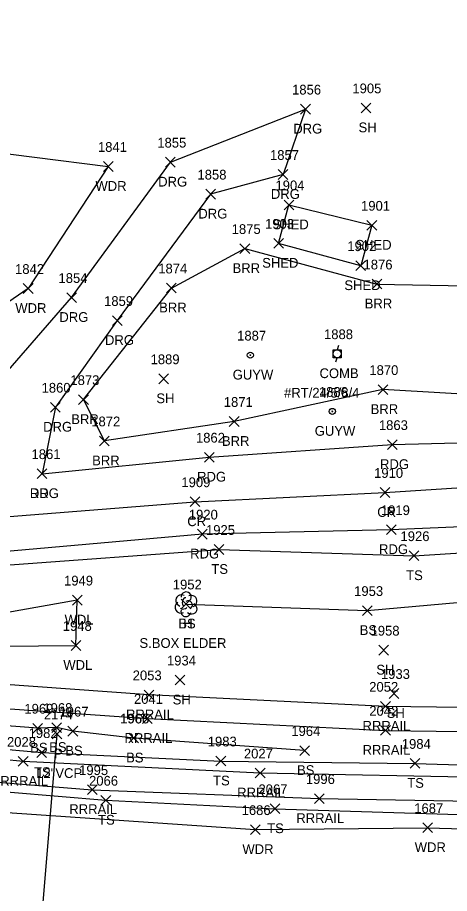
# Model space of a CAD drawing. Extents: x 1609623 to 1616187, y 756677 to 762826.
# Drawn here: x 1610056.5 to 1610145.1, y 761799.9 to 761979.6 of the extents above; entities that cross this region are included whole.
import ezdxf

# ---------------------------------------------------------------- set-up
doc = ezdxf.new("R2010")
doc.units = 0
for name, color, linetype in [('D_A', 7, 'Continuous'), ('D_C', 7, 'Continuous'), ('D_I', 7, 'Continuous'), ('D_TIC', 7, 'Continuous'), ('DCP', 7, 'Continuous'), ('L_A', 7, 'Continuous'), ('L_C', 7, 'Continuous'), ('L_I', 7, 'Continuous'), ('L_TIC', 7, 'Continuous'), ('LABL', 7, 'Continuous'), ('LAWA', 7, 'Continuous'), ('LBC', 7, 'Continuous'), ('LELB', 7, 'Continuous'), ('LTD', 7, 'Continuous'), ('P_A', 7, 'Continuous'), ('P_I', 7, 'Continuous'), ('P_TIC', 7, 'Continuous'), ('PEU', 7, 'Continuous'), ('PRC', 7, 'Continuous'), ('R_A', 7, 'Continuous'), ('R_I', 7, 'Continuous'), ('R_TIC', 7, 'Continuous'), ('RDG', 7, 'Continuous'), ('RR', 7, 'Continuous'), ('U_A', 7, 'Continuous'), ('U_C', 7, 'Continuous'), ('U_I', 7, 'Continuous'), ('UP', 7, 'Continuous'), ('UPGW', 7, 'Continuous')]:
    doc.layers.add(name, color=color, linetype=linetype)

msp = doc.modelspace()

# ---------------------------------------------------------------- linework, layer by layer
at = {"layer": 'D_TIC'}
for points in [[(1610063.58, 761831.63), (1610065.58, 761833.63)], [(1610065.58, 761831.63), (1610063.58, 761833.63)]]:
    msp.add_lwpolyline(points, dxfattribs=at)
at = {"layer": 'DCP'}
msp.add_lwpolyline([(1610064.58, 761832.63), (1610060.82, 761787.43)], dxfattribs=at)
at = {"layer": 'L_TIC'}
for points in [[(1610126.95, 761960.1), (1610128.95, 761962.1)], [(1610128.95, 761960.1), (1610126.95, 761962.1)], [(1610074.11, 761948.08), (1610076.11, 761950.08)], [(1610076.11, 761948.08), (1610074.11, 761950.08)], [(1610111.17, 761940.2), (1610113.17, 761942.2)], [(1610113.17, 761940.2), (1610111.17, 761942.2)], [(1610128.17, 761936.01), (1610130.17, 761938.01)], [(1610130.17, 761936.01), (1610128.17, 761938.01)], [(1610109.05, 761932.31), (1610111.05, 761934.31)], [(1610111.05, 761932.31), (1610109.05, 761934.31)], [(1610102.11, 761931.23), (1610104.11, 761933.23)], [(1610104.11, 761931.23), (1610102.11, 761933.23)], [(1610125.9, 761927.72), (1610127.9, 761929.72)], [(1610127.9, 761927.72), (1610125.9, 761929.72)], [(1610057.67, 761923.04), (1610059.67, 761925.04)], [(1610059.67, 761923.04), (1610057.67, 761925.04)], [(1610087.05, 761923.14), (1610089.05, 761925.14)], [(1610089.05, 761923.14), (1610087.05, 761925.14)], [(1610129.22, 761923.96), (1610131.22, 761925.96)], [(1610131.22, 761923.96), (1610129.22, 761925.96)], [(1610085.48, 761904.52), (1610087.48, 761906.52)], [(1610087.48, 761904.52), (1610085.48, 761906.52)], [(1610130.44, 761902.3), (1610132.44, 761904.3)], [(1610132.44, 761902.3), (1610130.44, 761904.3)], [(1610069.02, 761900.24), (1610071.02, 761902.24)], [(1610071.02, 761900.24), (1610069.02, 761902.24)], [(1610099.93, 761895.76), (1610101.93, 761897.76)], [(1610101.93, 761895.76), (1610099.93, 761897.76)], [(1610073.3, 761891.77), (1610075.3, 761893.77)], [(1610075.3, 761891.77), (1610073.3, 761893.77)], [(1610096.84, 761869.5), (1610098.84, 761871.5)], [(1610098.84, 761869.5), (1610096.84, 761871.5)], [(1610136.8, 761868.22), (1610138.8, 761870.22)], [(1610138.8, 761868.22), (1610136.8, 761870.22)], [(1610067.73, 761859.11), (1610069.73, 761861.11)], [(1610069.73, 761859.11), (1610067.73, 761861.11)], [(1610090.03, 761858.31), (1610092.03, 761860.31)], [(1610092.03, 761858.31), (1610090.03, 761860.31)], [(1610127.23, 761856.97), (1610129.23, 761858.97)], [(1610129.23, 761856.97), (1610127.23, 761858.97)], [(1610067.47, 761849.81), (1610069.47, 761851.81)], [(1610069.47, 761849.81), (1610067.47, 761851.81)], [(1610130.6, 761848.84), (1610132.6, 761850.84)], [(1610132.6, 761848.84), (1610130.6, 761850.84)], [(1610088.83, 761842.71), (1610090.83, 761844.71)], [(1610090.83, 761842.71), (1610088.83, 761844.71)], [(1610132.73, 761839.95), (1610134.73, 761841.95)], [(1610134.73, 761839.95), (1610132.73, 761841.95)], [(1610059.63, 761832.83), (1610061.63, 761834.83)], [(1610061.63, 761832.83), (1610059.63, 761834.83)], [(1610063.53, 761832.97), (1610065.53, 761834.97)], [(1610065.53, 761832.97), (1610063.53, 761834.97)], [(1610066.84, 761832.23), (1610068.84, 761834.23)], [(1610068.84, 761832.23), (1610066.84, 761834.23)], [(1610079.32, 761830.81), (1610081.32, 761832.81)], [(1610081.32, 761830.81), (1610079.32, 761832.81)], [(1610079.33, 761830.82), (1610081.33, 761832.82)], [(1610081.33, 761830.82), (1610079.33, 761832.82)], [(1610060.45, 761827.82), (1610062.45, 761829.82)], [(1610062.45, 761827.82), (1610060.45, 761829.82)], [(1610114.39, 761828.24), (1610116.39, 761830.24)], [(1610116.39, 761828.24), (1610114.39, 761830.24)], [(1610097.2, 761826.1), (1610099.2, 761828.1)], [(1610099.2, 761826.1), (1610097.2, 761828.1)], [(1610137.02, 761825.61), (1610139.02, 761827.61)], [(1610139.02, 761825.61), (1610137.02, 761827.61)], [(1610073.6, 761818.05), (1610075.6, 761820.05)], [(1610075.6, 761818.05), (1610073.6, 761820.05)], [(1610108.29, 761816.31), (1610110.29, 761818.31)], [(1610110.29, 761816.31), (1610108.29, 761818.31)], [(1610104.26, 761812.02), (1610106.26, 761814.02)], [(1610106.26, 761812.02), (1610104.26, 761814.02)], [(1610139.61, 761812.42), (1610141.61, 761814.42)], [(1610141.61, 761812.42), (1610139.61, 761814.42)]]:
    msp.add_lwpolyline(points, dxfattribs=at)
at = {"layer": 'LABL'}
msp.add_lwpolyline([(1610248.25, 761903.55), (1610212.86, 761902.85), (1610172.33, 761900.95), (1610131.44, 761903.3), (1610100.93, 761896.76), (1610074.3, 761892.77), (1610070.02, 761901.24), (1610088.05, 761924.14), (1610103.11, 761932.23), (1610130.22, 761924.96), (1610177.67, 761924.02), (1610222.12, 761925.25), (1610272.69, 761923.3), (1610298.02, 761931.54), (1610307.47, 761946.97), (1610343.23, 761952.19), (1610333.93, 761931.55), (1610306.47, 761919.59), (1610275.72, 761908.1)], dxfattribs=at)
at = {"layer": 'LAWA'}
for points in [[(1609992.55, 761894.87), (1609962.95, 761897.21), (1609938.68, 761910.93), (1609916.35, 761928.31), (1609882.7, 761954.17), (1609847.51, 761954.04), (1609857.22, 761979.64), (1609886.78, 761977.35), (1609922.36, 761966.26), (1609954.51, 761960.04), (1609988.47, 761965.16), (1610020.72, 761955.11), (1610044.76, 761952.87), (1610075.11, 761949.08), (1610058.67, 761924.04), (1610036.86, 761909.08), (1610036.53, 761893.37)], [(1609994.21, 761852.08), (1610030.01, 761850.47), (1610068.47, 761850.81), (1610068.73, 761860.11), (1610043.6, 761855.66), (1610020.13, 761857)], [(1610040.32, 761817.48), (1610105.26, 761813.02)], [(1610105.26, 761813.02), (1610140.61, 761813.42), (1610167.68, 761812.65), (1610195.19, 761811.82), (1610200.47, 761794.62), (1610201.65, 761767.6), (1610187.83, 761765.14), (1610147.91, 761771.28), (1610109.49, 761778.29), (1610068.49, 761778.93), (1610059.44, 761777.35), (1610050.54, 761771.19), (1610026.67, 761771.55), (1610012.41, 761775.03), (1609988.62, 761770.46), (1609964.66, 761759.68), (1609934.55, 761749.72), (1609900.52, 761743.76), (1609861.36, 761735.79), (1609834.63, 761731.47), (1609803.94, 761726.14)]]:
    msp.add_lwpolyline(points, dxfattribs=at)
at = {"layer": 'LBC'}
for points in [[(1610129.17, 761937.01), (1610126.9, 761928.72), (1610110.05, 761933.31), (1610112.17, 761941.2)], [(1610112.17, 761941.2), (1610129.17, 761937.01)]]:
    msp.add_lwpolyline(points, dxfattribs=at)
at = {"layer": 'LELB'}
for points in [[(1610013.78, 761861.49), (1610053.03, 761867.24), (1610097.84, 761870.5), (1610137.8, 761869.22), (1610175.38, 761871.56), (1610213.92, 761873.2)], [(1610115.39, 761829.24), (1610080.33, 761831.82), (1610080.32, 761831.81), (1610067.84, 761833.23), (1610064.53, 761833.97), (1610060.63, 761833.83), (1610021.62, 761836.75), (1609981.24, 761840.8), (1609944.38, 761844.79), (1609904, 761852.46), (1609862.59, 761859.91), (1609809.55, 761872.14), (1609808.99, 761869.38)], [(1609808.99, 761869.38), (1609856.47, 761857.61), (1609895.17, 761849.99), (1609941.57, 761842.59), (1609980.54, 761837.23), (1610021.92, 761832.42), (1610061.45, 761828.82), (1610098.2, 761827.1), (1610138.02, 761826.61), (1610177.04, 761825.41), (1610216.04, 761826.47), (1610216.04, 761826.46)], [(1610091.03, 761859.31), (1610128.23, 761857.97), (1610169.74, 761861.67), (1610201.97, 761864)], [(1609853.79, 761850.29), (1609899.31, 761840.85), (1609947.61, 761833.03), (1609998.93, 761826.28), (1610045.2, 761821.51), (1610074.6, 761819.05), (1610109.29, 761817.31), (1610149.22, 761816.09), (1610195.79, 761816.27), (1610226.8, 761817.5)]]:
    msp.add_lwpolyline(points, dxfattribs=at)
at = {"layer": 'LTD'}
msp.add_line((1610091.03, 761859.31), (1610091.03, 761859.31), dxfattribs=at)
msp.add_line((1610091.03, 761859.31), (1610091.03, 761859.31), dxfattribs=at)
msp.add_arc((1610091.08, 761860.74), 1.05, 335.5272, 180.9563, dxfattribs=at)
for centre, major_axis, ratio, start_param, end_param in [((1610090.24, 761859.98), (1.21, -0.51), 0.895232, 1.570796, 4.712389), ((1610090.82, 761859.77), (-0.208, -0.792), 0.645439, 3.141593, 6.283185), ((1610091.53, 761859.14), (-0.5, 0.667), 0.989748, 3.141593, 6.283185), ((1610092.07, 761859.89), (-1.14, -0.48), 0.949671, 1.570796, 4.712389), ((1610089.95, 761858.6), (0.58, -1.04), 0.959034, 3.141593, 6.283185), ((1610090.57, 761858.56), (-0.625, -0.083), 0.423636, 0, 3.141593), ((1610092.03, 761858.48), (-1.09, 0.79), 0.841452, 1.570796, 4.712389), ((1610091.03, 761857.81), (0.26, 1.06), 0.942809, 1.570796, 4.712389)]:
    msp.add_ellipse(centre, major_axis=major_axis, ratio=ratio, start_param=start_param, end_param=end_param, dxfattribs=at)
at = {"layer": 'P_TIC'}
for points in [[(1610132.36, 761891.01), (1610134.36, 761893.01)], [(1610134.36, 761891.01), (1610132.36, 761893.01)], [(1610094.83, 761888.43), (1610096.83, 761890.43)], [(1610096.83, 761888.43), (1610094.83, 761890.43)], [(1610060.53, 761885.05), (1610062.53, 761887.05)], [(1610062.53, 761885.05), (1610060.53, 761887.05)], [(1610130.85, 761881.19), (1610132.85, 761883.19)], [(1610132.85, 761881.19), (1610130.85, 761883.19)], [(1610091.88, 761879.29), (1610093.88, 761881.29)], [(1610093.88, 761879.29), (1610091.88, 761881.29)], [(1610093.41, 761872.65), (1610095.41, 761874.65)], [(1610095.41, 761872.65), (1610093.41, 761874.65)], [(1610132.16, 761873.56), (1610134.16, 761875.56)], [(1610134.16, 761873.56), (1610132.16, 761875.56)]]:
    msp.add_lwpolyline(points, dxfattribs=at)
at = {"layer": 'PEU'}
for points in [[(1610061.53, 761886.05), (1610095.83, 761889.43), (1610133.36, 761892.01), (1610173.59, 761893.05), (1610213.17, 761893.96), (1610248.92, 761897.46)], [(1610217, 761878.73), (1610174.77, 761876.33), (1610133.16, 761874.56), (1610094.41, 761873.65), (1610052.62, 761869.93), (1610013.35, 761867.91)]]:
    msp.add_lwpolyline(points, dxfattribs=at)
at = {"layer": 'PRC'}
msp.add_lwpolyline([(1610012.87, 761874.99), (1610052.18, 761877.05), (1610092.88, 761880.29), (1610131.85, 761882.19), (1610172.93, 761884.85), (1610214.04, 761887.46), (1610250.72, 761891.17)], dxfattribs=at)
at = {"layer": 'R_TIC'}
for points in [[(1610114.56, 761959.84), (1610116.56, 761961.84)], [(1610116.56, 761959.84), (1610114.56, 761961.84)], [(1610086.85, 761948.96), (1610088.85, 761950.96)], [(1610088.85, 761948.96), (1610086.85, 761950.96)], [(1610109.97, 761946.43), (1610111.97, 761948.43)], [(1610111.97, 761946.43), (1610109.97, 761948.43)], [(1610095.1, 761942.4), (1610097.1, 761944.4)], [(1610097.1, 761942.4), (1610095.1, 761944.4)], [(1610066.58, 761921.19), (1610068.58, 761923.19)], [(1610068.58, 761921.19), (1610066.58, 761923.19)], [(1610075.94, 761916.47), (1610077.94, 761918.47)], [(1610077.94, 761916.47), (1610075.94, 761918.47)], [(1610063.25, 761898.68), (1610065.25, 761900.68)], [(1610065.25, 761898.68), (1610063.25, 761900.68)], [(1610060.53, 761885.05), (1610062.53, 761887.05)], [(1610062.53, 761885.05), (1610060.53, 761887.05)], [(1610082.45, 761839.67), (1610084.45, 761841.67)], [(1610084.45, 761839.67), (1610082.45, 761841.67)], [(1610130.97, 761837.32), (1610132.97, 761839.32)], [(1610132.97, 761837.32), (1610130.97, 761839.32)], [(1610082.14, 761834.83), (1610084.14, 761836.83)], [(1610084.14, 761834.83), (1610082.14, 761836.83)], [(1610130.98, 761832.39), (1610132.98, 761834.39)], [(1610132.98, 761832.39), (1610130.98, 761834.39)], [(1610056.65, 761826.02), (1610058.65, 761828.02)], [(1610058.65, 761826.02), (1610056.65, 761828.02)], [(1610105.26, 761823.63), (1610107.26, 761825.63)], [(1610107.26, 761823.63), (1610105.26, 761825.63)], [(1610070.82, 761820.22), (1610072.82, 761822.22)], [(1610072.82, 761820.22), (1610070.82, 761822.22)], [(1610117.39, 761818.39), (1610119.39, 761820.39)], [(1610119.39, 761818.39), (1610117.39, 761820.39)]]:
    msp.add_lwpolyline(points, dxfattribs=at)
at = {"layer": 'RDG'}
msp.add_lwpolyline([(1610026.29, 761884.59), (1610045.08, 761896.36), (1610067.58, 761922.19), (1610087.85, 761949.96), (1610115.56, 761960.84), (1610110.97, 761947.43), (1610096.1, 761943.4), (1610076.94, 761917.47), (1610064.25, 761899.68), (1610061.53, 761886.05)], dxfattribs=at)
at = {"layer": 'RR'}
for points in [[(1610920.34, 761877.5), (1610875.2, 761880.63), (1610823.88, 761880.35), (1610770.14, 761877.16), (1610718.25, 761872.56), (1610624.39, 761862.75), (1610528.95, 761852.85), (1610433.45, 761843.38), (1610390.08, 761839.1), (1610343.15, 761834.31), (1610326.86, 761832.49), (1610295.2, 761829.73), (1610250.28, 761826.15), (1610201.81, 761823.95), (1610155.3, 761823.62), (1610106.26, 761824.63), (1610057.65, 761827.02), (1610007.52, 761831.91), (1609961.32, 761837.48), (1609915.47, 761844.69), (1609871.57, 761853.1), (1609828.18, 761862.73), (1609811.27, 761866.9)], [(1610356.77, 761837.2), (1610311.16, 761837.59), (1610274.66, 761838.51), (1610226.22, 761838.28), (1610178.94, 761837.67), (1610131.97, 761838.32), (1610083.45, 761840.67), (1610036.86, 761844.06), (1609989.49, 761848.51), (1609944.78, 761853.81), (1609900.87, 761860.46), (1609856.95, 761868.77), (1609813.49, 761878.61)], [(1609812.23, 761861.59), (1609849.51, 761852.68), (1609889.11, 761844.53), (1609934.67, 761836.61), (1609980.82, 761829.97), (1610026.24, 761824.91), (1610071.82, 761821.22), (1610118.39, 761819.39), (1610165.38, 761818.61), (1610213.1, 761819.4), (1610261.76, 761821.96), (1610309.94, 761826.07), (1610356.6, 761830.72), (1610389.15, 761834), (1610434.7, 761838.51), (1610480.7, 761843.13), (1610575.97, 761852.51), (1610672.94, 761862.83), (1610719.08, 761867.65), (1610767.25, 761871.97), (1610815.87, 761875.05), (1610864.69, 761875.82), (1610894.81, 761874.78)], [(1609812.59, 761873.79), (1609856.08, 761863.93), (1609900.7, 761855.53), (1609944.64, 761848.95), (1609989.39, 761843.6), (1610036.39, 761839.13), (1610083.14, 761835.83), (1610131.98, 761833.39), (1610178.86, 761832.74), (1610226.26, 761833.42), (1610274.6, 761833.63)]]:
    msp.add_lwpolyline(points, dxfattribs=at)
at = {"layer": 'UP'}
for p, q in [((1610122.3, 761912.33), (1610122.05, 761911.49)), ((1610121.22, 761909.83), (1610121.22, 761911.49)), ((1610121.22, 761911.49), (1610122.89, 761911.49)), ((1610122.05, 761910.66), (1610122.05, 761910.66)), ((1610122.89, 761911.49), (1610122.89, 761909.83)), ((1610122.89, 761909.83), (1610121.22, 761909.83)), ((1610121.8, 761908.99), (1610122.05, 761909.83))]:
    msp.add_line(p, q, dxfattribs=at)
msp.add_circle((1610122.05, 761910.66), 0.833, dxfattribs=at)
at = {"layer": 'UPGW'}
for centre, radius in [((1610104.24, 761910.37), 0.625), ((1610104.24, 761910.37), 0.0833), ((1610121.06, 761898.83), 0.625), ((1610121.06, 761898.83), 0.0833)]:
    msp.add_circle(centre, radius, dxfattribs=at)

# ---------------------------------------------------------------- texts
at = {"layer": 'D_A'}
msp.add_text('P', height=2, dxfattribs=at).set_placement((1610063.96, 761827.63))
at = {"layer": 'D_C'}
msp.add_text('12"VCP', height=2, dxfattribs=at).set_placement((1610060.32, 761823.63))
at = {"layer": 'D_I'}
msp.add_text('2174', height=2, dxfattribs=at).set_placement((1610061.89, 761835.63))
at = {"layer": 'L_A'}
for s, p in [('SH', (1610126.44, 761956.1)), ('WDR', (1610072.47, 761944.08)), ('SHED', (1610108.81, 761936.2)), ('SHED', (1610125.8, 761932.01)), ('SHED', (1610106.68, 761928.31)), ('BRR', (1610100.6, 761927.23)), ('SHED', (1610123.54, 761923.72)), ('BRR', (1610085.54, 761919.14)), ('BRR', (1610127.71, 761919.96)), ('WDR', (1610056.03, 761919.04)), ('SH', (1610084.97, 761900.52)), ('BRR', (1610128.93, 761898.3)), ('BRR', (1610067.51, 761896.24)), ('BRR', (1610098.42, 761891.76)), ('BRR', (1610071.79, 761887.77)), ('TS', (1610096.25, 761865.5)), ('TS', (1610136.21, 761864.22)), ('WDL', (1610066.14, 761855.11)), ('BS', (1610089.47, 761854.31)), ('H', (1610090.47, 761854.31)), ('BS', (1610126.68, 761852.97)), ('WDL', (1610065.88, 761845.81)), ('SH', (1610130.09, 761844.84)), ('SH', (1610088.32, 761838.71)), ('SH', (1610132.22, 761835.95)), ('BS', (1610059.07, 761828.83)), ('BS', (1610062.97, 761828.97)), ('BS', (1610066.28, 761828.23)), ('BS', (1610078.76, 761826.81)), ('BS', (1610078.77, 761826.82)), ('TS', (1610059.86, 761823.82)), ('BS', (1610113.83, 761824.24)), ('TS', (1610096.61, 761822.1)), ('TS', (1610136.43, 761821.61)), ('TS', (1610073.01, 761814.05)), ('TS', (1610107.7, 761812.31)), ('WDR', (1610102.62, 761808.02)), ('WDR', (1610137.97, 761808.42))]:
    msp.add_text(s, height=2, dxfattribs=at).set_placement(p)
at = {"layer": 'L_C'}
msp.add_text('S.BOX ELDER', height=2, dxfattribs=at).set_placement((1610081.5, 761850.31))
at = {"layer": 'L_I'}
for s, p in [('1905', (1610125.18, 761964.1)), ('1841', (1610072.98, 761952.08)), ('1904', (1610109.4, 761944.2)), ('1901', (1610126.96, 761940.01)), ('1875', (1610100.42, 761935.23)), ('1903', (1610107.27, 761936.31)), ('1902', (1610124.13, 761931.72)), ('1842', (1610055.98, 761927.04)), ('1874', (1610085.35, 761927.14)), ('1876', (1610127.47, 761927.96)), ('1889', (1610083.78, 761908.52)), ('1870', (1610128.66, 761906.3)), ('1873', (1610067.33, 761904.24)), ('1871', (1610098.8, 761899.76)), ('1872', (1610071.61, 761895.77)), ('1925', (1610095.15, 761873.5)), ('1926', (1610135.05, 761872.22)), ('1949', (1610066.03, 761863.11)), ('1952', (1610088.34, 761862.31)), ('1952', (1610088.34, 761862.31)), ('1953', (1610125.54, 761860.97)), ('1948', (1610065.77, 761853.81)), ('1958', (1610128.91, 761852.84)), ('1934', (1610087.14, 761846.71)), ('1933', (1610131.04, 761843.95)), ('1969', (1610057.89, 761836.83)), ('1968', (1610061.79, 761836.97)), ('1967', (1610065.1, 761836.23)), ('1966', (1610077.53, 761834.81)), ('1965', (1610077.59, 761834.82)), ('1982', (1610058.76, 761831.82)), ('1964', (1610112.65, 761832.24)), ('1983', (1610095.51, 761830.1)), ('1984', (1610135.32, 761829.61)), ('2066', (1610071.16, 761822.05)), ('2067', (1610105.91, 761820.31)), ('1686', (1610102.46, 761816.02)), ('1687', (1610137.87, 761816.42))]:
    msp.add_text(s, height=2, dxfattribs=at).set_placement(p)
at = {"layer": 'P_A'}
for s, p in [('RDG', (1610130.85, 761887.01)), ('RDG', (1610093.32, 761884.43)), ('RDG', (1610059.02, 761881.05)), ('CR', (1610130.28, 761877.19)), ('CR', (1610091.31, 761875.29)), ('RDG', (1610130.65, 761869.56)), ('RDG', (1610091.9, 761868.65))]:
    msp.add_text(s, height=2, dxfattribs=at).set_placement(p)
at = {"layer": 'P_I'}
for s, p in [('1863', (1610130.62, 761895.01)), ('1862', (1610093.09, 761892.43)), ('1861', (1610059.36, 761889.05)), ('1910', (1610129.63, 761885.19)), ('1909', (1610090.1, 761883.29)), ('1920', (1610091.63, 761876.65)), ('1919', (1610131.03, 761877.56))]:
    msp.add_text(s, height=2, dxfattribs=at).set_placement(p)
at = {"layer": 'R_A'}
for s, p in [('DRG', (1610113.05, 761955.84)), ('DRG', (1610085.34, 761944.96)), ('DRG', (1610108.46, 761942.43)), ('DRG', (1610093.58, 761938.4)), ('DRG', (1610065.07, 761917.19)), ('DRG', (1610074.43, 761912.47)), ('DRG', (1610061.74, 761894.68)), ('DRG', (1610059.02, 761881.05)), ('RRRAIL', (1610078.74, 761835.67)), ('RRRAIL', (1610127.26, 761833.32)), ('RRRAIL', (1610078.43, 761830.83)), ('RRRAIL', (1610127.27, 761828.39)), ('RRRAIL', (1610052.95, 761822.02)), ('RRRAIL', (1610101.55, 761819.63)), ('RRRAIL', (1610067.11, 761816.22)), ('RRRAIL', (1610113.68, 761814.39))]:
    msp.add_text(s, height=2, dxfattribs=at).set_placement(p)
at = {"layer": 'R_I'}
for s, p in [('1856', (1610112.81, 761963.84)), ('1855', (1610085.16, 761952.96)), ('1857', (1610108.28, 761950.43)), ('1858', (1610093.4, 761946.4)), ('1854', (1610064.89, 761925.19)), ('1859', (1610074.24, 761920.47)), ('1860', (1610061.42, 761902.68)), ('1861', (1610059.36, 761889.05)), ('2053', (1610080.11, 761843.67)), ('2052', (1610128.63, 761841.32)), ('2041', (1610080.37, 761838.83)), ('2042', (1610128.64, 761836.39)), ('2028', (1610054.32, 761830.02)), ('2027', (1610102.92, 761827.63)), ('1995', (1610069.12, 761824.22)), ('1996', (1610115.64, 761822.39))]:
    msp.add_text(s, height=2, dxfattribs=at).set_placement(p)
at = {"layer": 'U_A'}
for s, p in [('GUYW', (1610100.63, 761905.37)), ('COMB', (1610118.44, 761905.66)), ('GUYW', (1610117.46, 761893.83))]:
    msp.add_text(s, height=2, dxfattribs=at).set_placement(p)
at = {"layer": 'U_C'}
msp.add_text('#RT/24/5/8/4', height=2, dxfattribs=at).set_placement((1610111.17, 761901.66))
at = {"layer": 'U_I'}
for s, p in [('1888', (1610119.36, 761913.66)), ('1887', (1610101.54, 761913.37)), ('1886', (1610118.31, 761901.83))]:
    msp.add_text(s, height=2, dxfattribs=at).set_placement(p)

doc.saveas('drawing.dxf')
